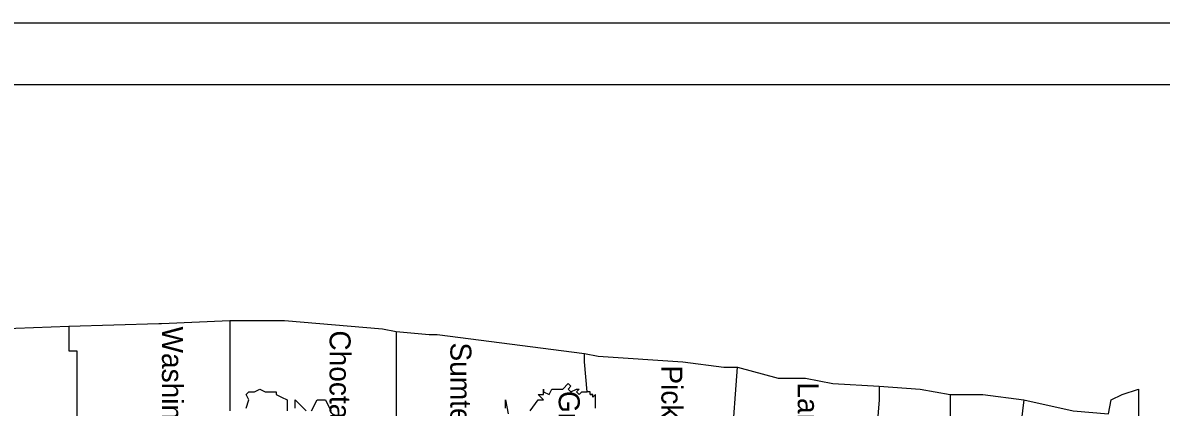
# Model space of a CAD drawing. Extents: x 0 to 0.917, y 0 to 0.708.
# Drawn here: x 0.3538 to 0.6361, y 0.6129 to 0.7083 of the extents above; entities that cross this region are included whole.
import ezdxf

# ---------------------------------------------------------------- set-up
doc = ezdxf.new("R2010")
doc.units = 0
for name, color, linetype in [('ANNO-SHT', 7, 'Continuous'), ('ANNO-TXT', 7, 'Continuous'), ('SHT-BDR', 7, 'Continuous'), ('SHT-FENCE', 7, 'Continuous')]:
    doc.layers.add(name, color=color, linetype=linetype)

msp = doc.modelspace()

# ---------------------------------------------------------------- linework, layer by layer
at = {"layer": 'ANNO-SHT'}
for points in [[(0.31583, 0.63102), (0.32192, 0.6317), (0.32192, 0.6317), (0.34764, 0.63238), (0.36523, 0.63306)], [(0.36523, 0.63306), (0.38756, 0.63374), (0.38824, 0.63374), (0.40515, 0.63442), (0.41124, 0.63442), (0.41869, 0.63442), (0.44305, 0.63238), (0.44643, 0.6317)], [(0.36523, 0.63306), (0.36523, 0.62695), (0.36726, 0.62695), (0.36726, 0.62288), (0.36726, 0.60931), (0.36794, 0.60795), (0.36929, 0.60727), (0.36861, 0.60659), (0.36861, 0.60388), (0.36997, 0.60388)], [(0.36523, 0.63306), (0.36523, 0.62695), (0.36726, 0.62695), (0.36726, 0.62288), (0.36726, 0.60931), (0.36794, 0.60795), (0.36929, 0.60727), (0.36861, 0.60659), (0.36861, 0.60388), (0.36997, 0.60388)], [(0.40515, 0.63442), (0.40515, 0.62492), (0.40515, 0.61202)], [(0.44643, 0.6317), (0.44643, 0.61745), (0.44643, 0.60252), (0.44711, 0.60388), (0.44778, 0.60388), (0.44778, 0.60523), (0.44914, 0.60523), (0.44914, 0.60659), (0.44981, 0.60795), (0.45049, 0.60863), (0.45117, 0.60931), (0.45387, 0.60931), (0.45523, 0.60931), (0.45658, 0.60795), (0.45658, 0.60795), (0.45726, 0.60727), (0.45726, 0.60659), (0.45793, 0.60388), (0.45861, 0.60388), (0.45929, 0.60252), (0.46132, 0.60116), (0.46132, 0.5998), (0.46132, 0.59777), (0.46199, 0.59845)], [(0.44643, 0.6317), (0.45455, 0.63102), (0.45658, 0.63102), (0.49312, 0.62627)], [(0.47959, 0.61202), (0.48162, 0.61474), (0.48297, 0.61474), (0.48162, 0.61609), (0.48162, 0.61609), (0.48297, 0.61609), (0.48297, 0.61745), (0.48297, 0.61745), (0.48297, 0.61677), (0.48432, 0.61609), (0.48432, 0.61609), (0.485, 0.61745), (0.48635, 0.61745), (0.48771, 0.61745), (0.48906, 0.61881), (0.48974, 0.61813), (0.48906, 0.61745), (0.48974, 0.61677), (0.49109, 0.61745), (0.49177, 0.61745), (0.49109, 0.61677), (0.49177, 0.61609), (0.49244, 0.61677), (0.4938, 0.61677), (0.49312, 0.62424), (0.49312, 0.62627)], [(0.49312, 0.62627), (0.4965, 0.62559), (0.51748, 0.62424), (0.52763, 0.62288), (0.53101, 0.62288), (0.53101, 0.62288), (0.54116, 0.62016), (0.54455, 0.62016), (0.54793, 0.62016), (0.5547, 0.61881), (0.5662, 0.61813)], [(0.52966, 0.6032), (0.52966, 0.60388), (0.53101, 0.62288)], [(0.40921, 0.6127), (0.40989, 0.61474), (0.40921, 0.61609), (0.40989, 0.61677), (0.41124, 0.61677), (0.4126, 0.61745), (0.41395, 0.61677), (0.41666, 0.61677), (0.41666, 0.61609), (0.41801, 0.61541), (0.41936, 0.61474), (0.41936, 0.61202)], [(0.49583, 0.6127), (0.49583, 0.61474), (0.49583, 0.61474), (0.49583, 0.61474), (0.49583, 0.61474), (0.49583, 0.61474), (0.49583, 0.61541), (0.49583, 0.61541), (0.49583, 0.61541), (0.49583, 0.61541), (0.49583, 0.61609), (0.49583, 0.61609), (0.49515, 0.61541), (0.49515, 0.61541), (0.49515, 0.61609), (0.49515, 0.61609), (0.49515, 0.61609), (0.49515, 0.61609), (0.49447, 0.61609), (0.49515, 0.61609), (0.49447, 0.61609), (0.49447, 0.61609), (0.49447, 0.61677), (0.4938, 0.61677), (0.4938, 0.61677), (0.4938, 0.61677)], [(0.5662, 0.61813), (0.5662, 0.61474), (0.56552, 0.60659), (0.56349, 0.60659), (0.56349, 0.60388), (0.55876, 0.60388), (0.55605, 0.60388), (0.55605, 0.60116), (0.55605, 0.59573), (0.55605, 0.59234), (0.55605, 0.58623)], [(0.5662, 0.61813), (0.5662, 0.61474), (0.56552, 0.60659), (0.56349, 0.60659), (0.56349, 0.60388), (0.55876, 0.60388), (0.55605, 0.60388), (0.55605, 0.60116), (0.55605, 0.59573), (0.55605, 0.59234), (0.55605, 0.58623)], [(0.5662, 0.61813), (0.57635, 0.61745), (0.58379, 0.61609)], [(0.58379, 0.61609), (0.58379, 0.60931), (0.58312, 0.60184), (0.58312, 0.60116), (0.58312, 0.59437), (0.58312, 0.59166), (0.58312, 0.59166), (0.58312, 0.58962), (0.58312, 0.58555), (0.58312, 0.58216), (0.58244, 0.57944)], [(0.58379, 0.61609), (0.59191, 0.61609), (0.60206, 0.61474), (0.61424, 0.61202), (0.62304, 0.61134), (0.62372, 0.61474), (0.62642, 0.61609), (0.63048, 0.61745), (0.63048, 0.60184), (0.63048, 0.59573), (0.63048, 0.58759), (0.63048, 0.57876), (0.63048, 0.56994), (0.62981, 0.56247), (0.62981, 0.5618)], [(0.42139, 0.6127), (0.42139, 0.61474), (0.42139, 0.61474), (0.4241, 0.61202)], [(0.42545, 0.61202), (0.42681, 0.61474), (0.42816, 0.61474), (0.42884, 0.61474), (0.43019, 0.61202)], [(0.4735, 0.6127), (0.4735, 0.61474), (0.47417, 0.61134)], [(0.60206, 0.61474), (0.60071, 0.60388), (0.60071, 0.58759), (0.60003, 0.57944)]]:
    msp.add_lwpolyline(points, dxfattribs=at)
at = {"layer": 'SHT-BDR'}
msp.add_lwpolyline([(0.01986, 0.69298), (0.89679, 0.69298), (0.89679, 0.01536), (0.01986, 0.01536)], close=True, dxfattribs=at)
at = {"layer": 'SHT-FENCE'}
msp.add_lwpolyline([(0, 0.70833), (0.91666, 0.70833), (0.91666, 0), (0, 0)], close=True, dxfattribs=at)

# ---------------------------------------------------------------- texts
at = {"layer": 'ANNO-TXT'}
for s, p in [('Washington', (0.38834, 0.63297)), ('Choctaw', (0.4299, 0.632)), ('Sumter', (0.45984, 0.62901)), ('Pickens', (0.51217, 0.62332)), ('Lamar', (0.54599, 0.61909)), ('Greene', (0.48671, 0.61699))]:
    msp.add_text(s, height=0.005208, rotation=270, dxfattribs=at).set_placement(p)

doc.saveas('drawing.dxf')
